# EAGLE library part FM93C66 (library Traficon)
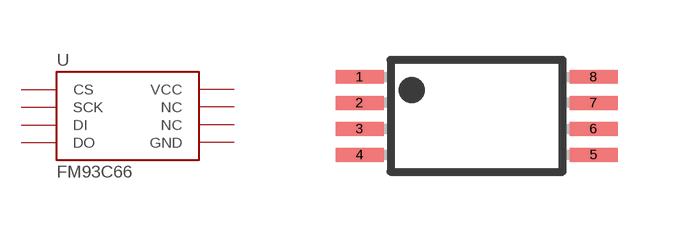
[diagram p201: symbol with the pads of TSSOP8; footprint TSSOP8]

Designator prefix U

## FM93C66  [TSSOP8]
1  CS
2  SCK
3  DI
4  DO
5  GND
6  NC
7  NC
8  VCC

## Footprint TSSOP8 (pad centres in mm)
Plastic Small Outline
smd 1.2 x 0.35: 1 -2.925,0.975; 2 -2.925,0.325; 3 -2.925,-0.325; 4 -2.925,-0.975; 5 2.925,-0.975; 6 2.925,-0.325; 7 2.925,0.325; 8 2.925,0.975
